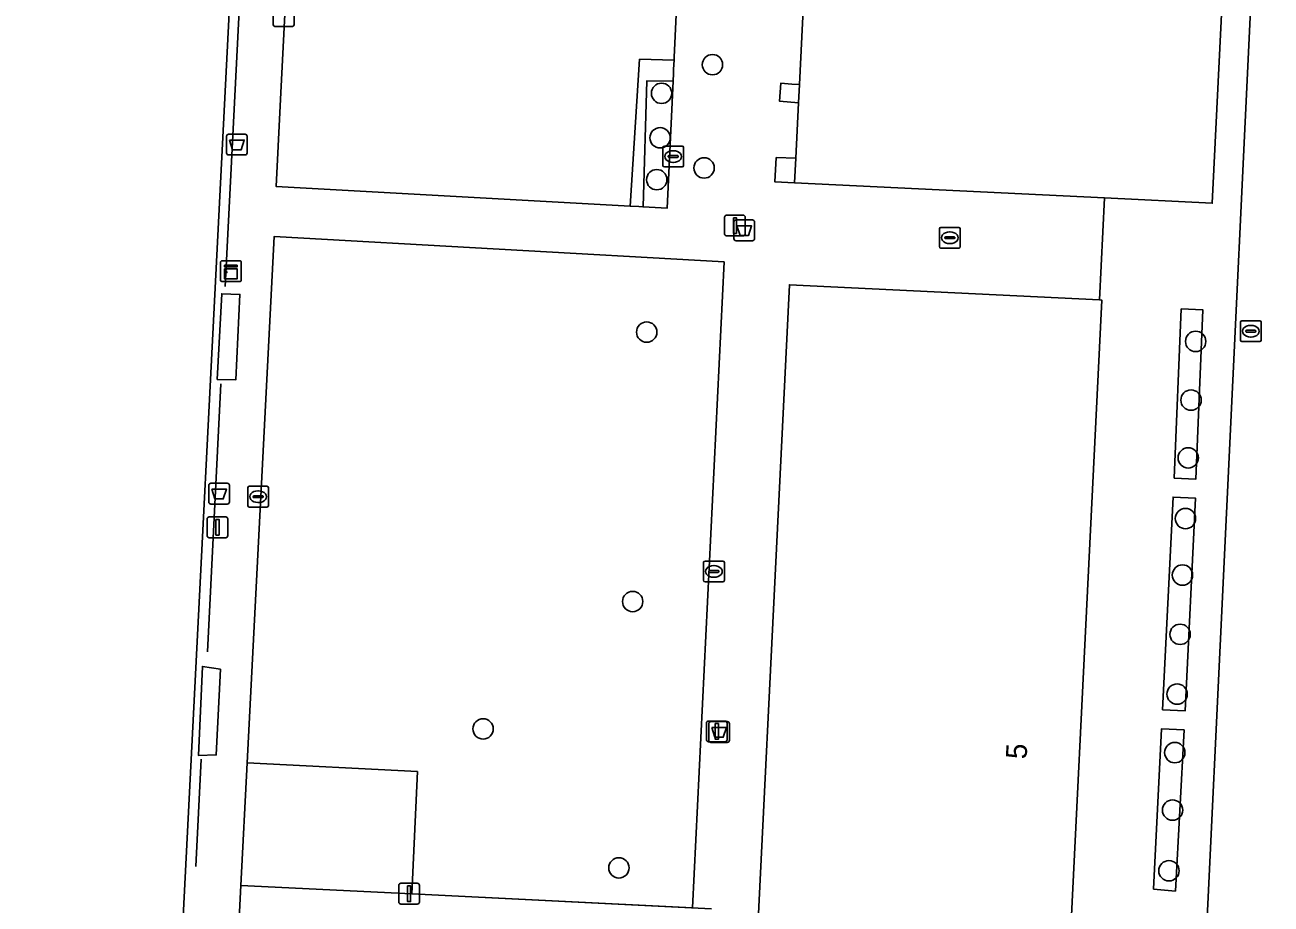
# Model space of a CAD drawing. Extents: x 161758 to 162722, y 384793 to 385405.
# Drawn here: x 162339.8 to 162399.6, y 385038.7 to 385080.9 of the extents above; entities that cross this region are included whole.
import ezdxf

# ---------------------------------------------------------------- set-up
doc = ezdxf.new("R2010")
doc.units = 0
for name, color, linetype in [('IMGEO_Afvalbak', 7, 'Continuous'), ('IMGEO_Boom', 7, 'Continuous'), ('IMGEO_Groenvoorziening', 7, 'Continuous'), ('IMGEO_Haag', 7, 'Continuous'), ('IMGEO_Hek', 7, 'Continuous'), ('IMGEO_Kast', 7, 'Continuous'), ('IMGEO_Kolk', 7, 'Continuous'), ('IMGEO_Lichtmast', 7, 'Continuous'), ('IMGEO_Pand', 7, 'Continuous'), ('IMGEO_Pand_nummerreeks', 7, 'Continuous'), ('IMGEO_Rioolput', 7, 'Continuous'), ('IMGEO_Terreindeel_open', 7, 'Continuous'), ('IMGEO_Voetpad_open', 7, 'Continuous')]:
    doc.layers.add(name, color=color, linetype=linetype)

msp = doc.modelspace()

# ---------------------------------------------------------------- linework, layer by layer
at = {"layer": 'IMGEO_Afvalbak'}
for p, q in [((162349.493, 385074.776), (162349.493, 385075.576)), ((162349.493, 385075.576), (162349.493, 385074.776)), ((162349.593, 385075.676), (162350.383, 385075.676)), ((162350.383, 385075.676), (162349.593, 385075.676)), ((162350.483, 385075.576), (162350.483, 385074.776)), ((162350.483, 385074.776), (162350.483, 385075.576)), ((162350.383, 385074.676), (162349.593, 385074.676)), ((162349.593, 385074.676), (162350.383, 385074.676)), ((162373.853, 385070.657), (162373.853, 385071.457)), ((162373.853, 385071.457), (162373.853, 385070.657)), ((162373.953, 385071.557), (162374.743, 385071.557)), ((162374.743, 385071.557), (162373.953, 385071.557)), ((162374.843, 385071.457), (162374.843, 385070.657)), ((162374.843, 385070.657), (162374.843, 385071.457)), ((162374.743, 385070.557), (162373.953, 385070.557)), ((162373.953, 385070.557), (162374.743, 385070.557)), ((162348.638, 385058.009), (162348.638, 385058.809)), ((162348.638, 385058.809), (162348.638, 385058.009)), ((162348.738, 385058.909), (162349.528, 385058.909)), ((162349.528, 385058.909), (162348.738, 385058.909)), ((162349.628, 385058.809), (162349.628, 385058.009)), ((162349.628, 385058.009), (162349.628, 385058.809)), ((162349.528, 385057.909), (162348.738, 385057.909)), ((162348.738, 385057.909), (162349.528, 385057.909)), ((162372.645, 385046.557), (162372.645, 385047.357)), ((162372.645, 385047.357), (162372.645, 385046.557)), ((162372.745, 385047.457), (162373.535, 385047.457)), ((162373.535, 385047.457), (162372.745, 385047.457)), ((162373.635, 385047.357), (162373.635, 385046.557)), ((162373.635, 385046.557), (162373.635, 385047.357)), ((162373.535, 385046.457), (162372.745, 385046.457)), ((162372.745, 385046.457), (162373.535, 385046.457))]:
    msp.add_line(p, q, dxfattribs=at)
for points in [[(162349.636, 385075.39), (162350.34, 385075.39), (162350.191, 385074.92), (162349.785, 385074.92), (162349.636, 385075.39)], [(162373.996, 385071.271), (162374.7, 385071.271), (162374.551, 385070.801), (162374.145, 385070.801), (162373.996, 385071.271)], [(162348.781, 385058.623), (162349.485, 385058.623), (162349.336, 385058.153), (162348.93, 385058.153), (162348.781, 385058.623)], [(162372.788, 385047.171), (162373.492, 385047.171), (162373.343, 385046.701), (162372.937, 385046.701), (162372.788, 385047.171)]]:
    msp.add_lwpolyline(points, dxfattribs=at)
for centre, start, end in [((162349.593, 385075.576), 90, 180), ((162349.593, 385075.576), 90, 180), ((162350.383, 385075.576), 0, 90), ((162350.383, 385075.576), 360, 90), ((162349.593, 385074.776), 180, 270), ((162349.593, 385074.776), 180, 270), ((162350.383, 385074.776), 270, 0), ((162350.383, 385074.776), 270, 0), ((162373.953, 385071.457), 90, 180), ((162373.953, 385071.457), 90, 180), ((162374.743, 385071.457), 0, 90), ((162374.743, 385071.457), 360, 90), ((162373.953, 385070.657), 180, 270), ((162373.953, 385070.657), 180, 270), ((162374.743, 385070.657), 270, 0), ((162374.743, 385070.657), 270, 0), ((162348.738, 385058.809), 90, 180), ((162348.738, 385058.809), 90, 180), ((162349.528, 385058.809), 0, 90), ((162349.528, 385058.809), 360, 90), ((162348.738, 385058.009), 180, 270), ((162348.738, 385058.009), 180, 270), ((162349.528, 385058.009), 270, 0), ((162349.528, 385058.009), 270, 0), ((162372.745, 385047.357), 90, 180), ((162372.745, 385047.357), 90, 180), ((162373.535, 385047.357), 0, 90), ((162373.535, 385047.357), 360, 90), ((162372.745, 385046.557), 180, 270), ((162372.745, 385046.557), 180, 270), ((162373.535, 385046.557), 270, 0), ((162373.535, 385046.557), 270, 0)]:
    msp.add_arc(centre, 0.1, start, end, dxfattribs=at)
at = {"layer": 'IMGEO_Boom'}
for centre in [(162372.823, 385079.014), (162370.38, 385077.639), (162370.308, 385075.501), (162372.42, 385074.053), (162370.146, 385073.49), (162369.665, 385066.169), (162396.02, 385065.722), (162395.798, 385062.901), (162395.663, 385060.125), (162395.531, 385057.208), (162395.387, 385054.497), (162368.992, 385053.223), (162395.273, 385051.648), (162395.13, 385048.778), (162361.809, 385047.104), (162395.018, 385045.966), (162394.914, 385043.207), (162368.33, 385040.429), (162394.739, 385040.291)]:
    msp.add_circle(centre, 0.489, dxfattribs=at)
at = {"layer": 'IMGEO_Groenvoorziening'}
msp.add_lwpolyline([(162353.845, 385111.893), (162352.061, 385077.041), (162351.881, 385073.156), (162368.869, 385072.219), (162369.32, 385079.274), (162370.979, 385079.226), (162370.986, 385079.375), (162371.082, 385081.416)], dxfattribs=at)
for points in [[(162370.931, 385078.223), (162370.949, 385078.593), (162370.958, 385078.793), (162370.979, 385079.226), (162369.32, 385079.274), (162368.869, 385072.219), (162369.289, 385072.196), (162369.489, 385072.185), (162369.672, 385078.24)], [(162370.931, 385078.223), (162369.672, 385078.24), (162369.489, 385072.185), (162370.642, 385072.121)], [(162376.996, 385078.06), (162376.628, 385078.086), (162376.1, 385078.123), (162376.047, 385077.257), (162376.953, 385077.182)], [(162376.822, 385074.53), (162375.882, 385074.555), (162375.811, 385073.388), (162376.764, 385073.346)], [(162373.384, 385069.543), (162351.779, 385070.756), (162350.477, 385045.47), (162358.655, 385045.052), (162358.391, 385039.179), (162371.859, 385038.506)], [(162396.368, 385067.236), (162395.326, 385067.279), (162394.991, 385059.153), (162396.033, 385059.11)], [(162396.02, 385058.186), (162394.94, 385058.24), (162394.429, 385048.024), (162395.509, 385047.97)], [(162395.464, 385047.056), (162394.385, 385047.109), (162394, 385039.407), (162395.052, 385039.311)]]:
    msp.add_lwpolyline(points, close=True, dxfattribs=at)
at = {"layer": 'IMGEO_Haag'}
for points in [[(162369.672, 385078.24), (162370.931, 385078.223), (162370.949, 385078.593), (162370.958, 385078.793), (162370.979, 385079.226), (162369.32, 385079.274), (162368.869, 385072.219), (162369.289, 385072.196), (162369.489, 385072.185)], [(162396.368, 385067.236), (162395.326, 385067.279), (162394.991, 385059.153), (162396.033, 385059.11)], [(162396.02, 385058.186), (162394.94, 385058.24), (162394.429, 385048.024), (162395.509, 385047.97)], [(162395.464, 385047.056), (162394.385, 385047.109), (162394, 385039.407), (162395.052, 385039.311)]]:
    msp.add_lwpolyline(points, close=True, dxfattribs=at)
at = {"layer": 'IMGEO_Hek'}
for points in [[(162349.435, 385068.365), (162351.591, 385110.949), (162328.352, 385112.223)], [(162391.403, 385067.713), (162391.641, 385072.611)], [(162348.578, 385050.813), (162349.22, 385063.679)], [(162348.022, 385040.498), (162348.27, 385045.648)], [(162344.943, 384881.973), (162351.819, 385022.72), (162349.339, 385022.849), (162350.174, 385039.589), (162358.391, 385039.179), (162372.781, 385038.462)]]:
    msp.add_lwpolyline(points, dxfattribs=at)
at = {"layer": 'IMGEO_Kast'}
for p, q in [((162349.201, 385068.668), (162349.201, 385069.509)), ((162349.201, 385069.509), (162349.201, 385068.668)), ((162349.276, 385069.593), (162350.117, 385069.593)), ((162350.117, 385069.593), (162349.276, 385069.593)), ((162350.201, 385069.518), (162350.201, 385068.677)), ((162350.201, 385068.677), (162350.201, 385069.518)), ((162350.126, 385068.593), (162349.285, 385068.593)), ((162349.285, 385068.593), (162350.126, 385068.593))]:
    msp.add_line(p, q, dxfattribs=at)
for points in [[(162349.396, 385069.383), (162349.996, 385069.383), (162349.996, 385069.298), (162349.396, 385069.298), (162349.396, 385069.383)], [(162349.396, 385069.208), (162349.996, 385069.208), (162349.996, 385068.719), (162349.396, 385068.719), (162349.396, 385069.208)]]:
    msp.add_lwpolyline(points, dxfattribs=at)
msp.add_circle((162349.48, 385069.057), 0.0377, dxfattribs=at)
for centre, start, end in [((162349.279, 385069.515), 92.4484, 184.28452), ((162349.279, 385069.515), 92.4484, 184.28452), ((162350.123, 385069.515), 2.4484, 94.28452), ((162350.123, 385069.515), 2.4484, 94.28452), ((162349.279, 385068.671), 182.4484, 274.28452), ((162349.279, 385068.671), 182.4484, 274.28452), ((162350.123, 385068.671), 272.4484, 4.28452), ((162350.123, 385068.671), 272.4484, 4.28452)]:
    msp.add_arc(centre, 0.0779, start, end, dxfattribs=at)
at = {"layer": 'IMGEO_Kolk'}
for p, q in [((162351.736, 385080.925), (162351.736, 385081.777)), ((162352.737, 385081.777), (162352.737, 385080.925)), ((162352.663, 385080.851), (162351.811, 385080.851)), ((162370.437, 385074.176), (162370.437, 385075.028)), ((162370.512, 385075.102), (162371.364, 385075.102)), ((162370.925, 385074.882), (162370.95, 385074.882)), ((162371.438, 385075.028), (162371.438, 385074.176)), ((162370.696, 385074.596), (162370.696, 385074.608)), ((162371.134, 385074.559), (162370.736, 385074.559)), ((162370.739, 385074.645), (162371.137, 385074.645)), ((162370.948, 385074.322), (162370.923, 385074.322)), ((162371.18, 385074.608), (162371.18, 385074.596)), ((162371.364, 385074.102), (162370.512, 385074.102)), ((162383.719, 385070.274), (162383.719, 385071.126)), ((162383.794, 385071.2), (162384.646, 385071.2)), ((162383.978, 385070.694), (162383.978, 385070.706)), ((162384.416, 385070.657), (162384.018, 385070.657)), ((162384.021, 385070.743), (162384.419, 385070.743)), ((162384.207, 385070.98), (162384.232, 385070.98)), ((162384.462, 385070.706), (162384.462, 385070.694)), ((162384.72, 385071.126), (162384.72, 385070.274)), ((162384.646, 385070.2), (162383.794, 385070.2)), ((162384.23, 385070.42), (162384.205, 385070.42)), ((162350.583, 385058.76), (162351.435, 385058.76)), ((162350.508, 385057.834), (162350.508, 385058.686)), ((162350.767, 385058.254), (162350.767, 385058.266)), ((162351.205, 385058.217), (162350.807, 385058.217)), ((162350.81, 385058.303), (162351.208, 385058.303)), ((162350.996, 385058.54), (162351.021, 385058.54)), ((162351.251, 385058.266), (162351.251, 385058.254)), ((162351.509, 385058.686), (162351.509, 385057.834)), ((162351.435, 385057.76), (162350.583, 385057.76)), ((162351.019, 385057.98), (162350.994, 385057.98)), ((162372.467, 385055.169), (162373.319, 385055.169)), ((162372.392, 385054.243), (162372.392, 385055.095)), ((162372.651, 385054.663), (162372.651, 385054.675)), ((162373.089, 385054.626), (162372.691, 385054.626)), ((162372.694, 385054.712), (162373.092, 385054.712)), ((162372.88, 385054.949), (162372.905, 385054.949)), ((162373.135, 385054.675), (162373.135, 385054.663)), ((162373.393, 385055.095), (162373.393, 385054.243)), ((162373.319, 385054.169), (162372.467, 385054.169)), ((162372.903, 385054.389), (162372.878, 385054.389))]:
    msp.add_line(p, q, dxfattribs=at)
for points in [[(162351.736, 385080.925), (162351.736, 385081.777)], [(162352.737, 385081.777), (162352.737, 385080.925)], [(162352.663, 385080.851), (162351.811, 385080.851)], [(162370.437, 385074.176), (162370.437, 385075.028)], [(162370.512, 385075.102), (162371.364, 385075.102)], [(162371.438, 385075.028), (162371.438, 385074.176)], [(162371.364, 385074.102), (162370.512, 385074.102)], [(162383.719, 385070.274), (162383.719, 385071.126)], [(162383.794, 385071.2), (162384.646, 385071.2)], [(162384.72, 385071.126), (162384.72, 385070.274)], [(162384.646, 385070.2), (162383.794, 385070.2)], [(162350.583, 385058.76), (162351.435, 385058.76)], [(162350.508, 385057.834), (162350.508, 385058.686)], [(162351.509, 385058.686), (162351.509, 385057.834)], [(162351.435, 385057.76), (162350.583, 385057.76)], [(162372.467, 385055.169), (162373.319, 385055.169)], [(162372.392, 385054.243), (162372.392, 385055.095)], [(162373.393, 385055.095), (162373.393, 385054.243)], [(162373.319, 385054.169), (162372.467, 385054.169)]]:
    msp.add_lwpolyline(points, dxfattribs=at)
for centre, radius, start, end in [((162351.813, 385080.927), 0.0765, 181.55205, 268.44795), ((162351.813, 385080.927), 0.0765, 181.55205, 268.44795), ((162352.661, 385080.927), 0.0765, 271.55205, 358.44795), ((162352.661, 385080.927), 0.0765, 271.55205, 358.44795), ((162370.514, 385075.026), 0.0765, 91.55205, 178.44795), ((162370.514, 385075.026), 0.0765, 91.55205, 178.44795), ((162371.362, 385075.026), 0.0765, 1.55205, 88.44795), ((162371.362, 385075.026), 0.0765, 1.55205, 88.44795), ((162370.736, 385074.605), 0.0403, 85.87752, 175.75265), ((162370.733, 385074.595), 0.0366, 178.93798, 274.71019), ((162371.137, 385074.602), 0.043, 264.86636, 352.45326), ((162371.141, 385074.607), 0.0386, 1.73085, 96.63898), ((162370.514, 385074.178), 0.0765, 181.55205, 268.44795), ((162370.514, 385074.178), 0.0765, 181.55205, 268.44795), ((162371.362, 385074.178), 0.0765, 271.55205, 358.44795), ((162371.362, 385074.178), 0.0765, 271.55205, 358.44795), ((162383.796, 385071.124), 0.0765, 91.55205, 178.44795), ((162383.796, 385071.124), 0.0765, 91.55205, 178.44795), ((162384.018, 385070.703), 0.0403, 85.87752, 175.75265), ((162384.015, 385070.693), 0.0366, 178.93798, 274.71019), ((162384.419, 385070.7), 0.043, 264.86636, 352.45326), ((162384.423, 385070.705), 0.0386, 1.73085, 96.63898), ((162384.644, 385071.124), 0.0765, 1.55205, 88.44795), ((162384.644, 385071.124), 0.0765, 1.55205, 88.44795), ((162383.796, 385070.276), 0.0765, 181.55205, 268.44795), ((162383.796, 385070.276), 0.0765, 181.55205, 268.44795), ((162384.644, 385070.276), 0.0765, 271.55205, 358.44795), ((162384.644, 385070.276), 0.0765, 271.55205, 358.44795), ((162350.585, 385058.684), 0.0765, 91.55205, 178.44795), ((162350.585, 385058.684), 0.0765, 91.55205, 178.44795), ((162351.433, 385058.684), 0.0765, 1.55205, 88.44795), ((162351.433, 385058.684), 0.0765, 1.55205, 88.44795), ((162350.807, 385058.263), 0.0403, 85.87752, 175.75265), ((162350.804, 385058.253), 0.0366, 178.93798, 274.71019), ((162351.208, 385058.26), 0.043, 264.86636, 352.45326), ((162351.212, 385058.265), 0.0386, 1.73085, 96.63898), ((162350.585, 385057.836), 0.0765, 181.55205, 268.44795), ((162350.585, 385057.836), 0.0765, 181.55205, 268.44795), ((162351.433, 385057.836), 0.0765, 271.55205, 358.44795), ((162351.433, 385057.836), 0.0765, 271.55205, 358.44795), ((162372.469, 385055.093), 0.0765, 91.55205, 178.44795), ((162372.469, 385055.093), 0.0765, 91.55205, 178.44795), ((162373.317, 385055.093), 0.0765, 1.55205, 88.44795), ((162373.317, 385055.093), 0.0765, 1.55205, 88.44795), ((162372.691, 385054.672), 0.0403, 85.87752, 175.75265), ((162372.688, 385054.662), 0.0366, 178.93798, 274.71019), ((162373.092, 385054.669), 0.043, 264.86636, 352.45326), ((162373.096, 385054.674), 0.0386, 1.73085, 96.63898), ((162372.469, 385054.245), 0.0765, 181.55205, 268.44795), ((162372.469, 385054.245), 0.0765, 181.55205, 268.44795), ((162373.317, 385054.245), 0.0765, 271.55205, 358.44795), ((162373.317, 385054.245), 0.0765, 271.55205, 358.44795)]:
    msp.add_arc(centre, radius, start, end, dxfattribs=at)
for centre, major_axis, ratio, start_param, end_param in [((162370.924, 385074.602), (-0.387, 0.002), 0.722429, 4.712389, 7.853982), ((162370.949, 385074.602), (-0.39, 0.002), 0.717154, 1.570796, 4.712389), ((162384.206, 385070.7), (-0.387, 0.002), 0.722429, 4.712389, 7.853982), ((162384.231, 385070.7), (-0.39, 0.002), 0.717154, 1.570796, 4.712389), ((162350.995, 385058.26), (-0.387, 0.002), 0.722429, 4.712389, 7.853982), ((162351.02, 385058.26), (-0.39, 0.002), 0.717154, 1.570796, 4.712389), ((162372.879, 385054.669), (-0.387, 0.002), 0.722429, 4.712389, 7.853982), ((162372.904, 385054.669), (-0.39, 0.002), 0.717154, 1.570796, 4.712389)]:
    msp.add_ellipse(centre, major_axis=major_axis, ratio=ratio, start_param=start_param, end_param=end_param, dxfattribs=at)
at = {"layer": 'IMGEO_Lichtmast'}
for p, q in [((162373.406, 385070.887), (162373.406, 385071.687)), ((162373.406, 385071.687), (162373.406, 385070.887)), ((162373.506, 385071.787), (162374.296, 385071.787)), ((162374.296, 385071.787), (162373.506, 385071.787)), ((162374.396, 385071.687), (162374.396, 385070.887)), ((162374.396, 385070.887), (162374.396, 385071.687)), ((162374.296, 385070.787), (162373.506, 385070.787)), ((162373.506, 385070.787), (162374.296, 385070.787)), ((162348.562, 385056.391), (162348.562, 385057.191)), ((162348.562, 385057.191), (162348.562, 385056.391)), ((162348.662, 385057.291), (162349.452, 385057.291)), ((162349.452, 385057.291), (162348.662, 385057.291)), ((162349.552, 385057.191), (162349.552, 385056.391)), ((162349.552, 385056.391), (162349.552, 385057.191)), ((162349.452, 385056.291), (162348.662, 385056.291)), ((162348.662, 385056.291), (162349.452, 385056.291)), ((162372.536, 385046.585), (162372.536, 385047.385)), ((162372.536, 385047.385), (162372.536, 385046.585)), ((162372.636, 385047.485), (162373.426, 385047.485)), ((162373.426, 385047.485), (162372.636, 385047.485)), ((162373.526, 385047.385), (162373.526, 385046.585)), ((162373.526, 385046.585), (162373.526, 385047.385)), ((162373.426, 385046.485), (162372.636, 385046.485)), ((162372.636, 385046.485), (162373.426, 385046.485)), ((162357.762, 385038.789), (162357.762, 385039.589)), ((162357.762, 385039.589), (162357.762, 385038.789)), ((162357.862, 385039.689), (162358.652, 385039.689)), ((162358.652, 385039.689), (162357.862, 385039.689)), ((162358.752, 385039.589), (162358.752, 385038.789)), ((162358.752, 385038.789), (162358.752, 385039.589)), ((162358.652, 385038.689), (162357.862, 385038.689)), ((162357.862, 385038.689), (162358.652, 385038.689))]:
    msp.add_line(p, q, dxfattribs=at)
for points in [[(162373.826, 385071.662), (162373.976, 385071.662), (162373.976, 385070.912), (162373.826, 385070.912), (162373.826, 385071.662)], [(162348.982, 385057.166), (162349.132, 385057.166), (162349.132, 385056.416), (162348.982, 385056.416), (162348.982, 385057.166)], [(162372.956, 385047.36), (162373.106, 385047.36), (162373.106, 385046.61), (162372.956, 385046.61), (162372.956, 385047.36)], [(162358.182, 385039.564), (162358.332, 385039.564), (162358.332, 385038.814), (162358.182, 385038.814), (162358.182, 385039.564)]]:
    msp.add_lwpolyline(points, dxfattribs=at)
for centre, start, end in [((162373.506, 385071.687), 90, 180), ((162373.506, 385071.687), 90, 180), ((162374.296, 385071.687), 0, 90), ((162374.296, 385071.687), 360, 90), ((162373.506, 385070.887), 180, 270), ((162373.506, 385070.887), 180, 270), ((162374.296, 385070.887), 270, 0), ((162374.296, 385070.887), 270, 0), ((162348.662, 385057.191), 90, 180), ((162348.662, 385057.191), 90, 180), ((162349.452, 385057.191), 0, 90), ((162349.452, 385057.191), 360, 90), ((162348.662, 385056.391), 180, 270), ((162348.662, 385056.391), 180, 270), ((162349.452, 385056.391), 270, 0), ((162349.452, 385056.391), 270, 0), ((162372.636, 385047.385), 90, 180), ((162372.636, 385047.385), 90, 180), ((162373.426, 385047.385), 0, 90), ((162373.426, 385047.385), 360, 90), ((162372.636, 385046.585), 180, 270), ((162372.636, 385046.585), 180, 270), ((162373.426, 385046.585), 270, 0), ((162373.426, 385046.585), 270, 0), ((162357.862, 385039.589), 90, 180), ((162357.862, 385039.589), 90, 180), ((162358.652, 385039.589), 0, 90), ((162358.652, 385039.589), 360, 90), ((162357.862, 385038.789), 180, 270), ((162357.862, 385038.789), 180, 270), ((162358.652, 385038.789), 270, 0), ((162358.652, 385038.789), 270, 0)]:
    msp.add_arc(centre, 0.1, start, end, dxfattribs=at)
at = {"layer": 'IMGEO_Pand'}
for points in [[(162398.207, 385100.548), (162387.283, 385101.087), (162378.156, 385101.538), (162377.464, 385087.529), (162377.462, 385087.485), (162377.453, 385087.31), (162377.415, 385086.541), (162377.292, 385084.054), (162377.19, 385081.987), (162376.996, 385078.06), (162376.953, 385077.182), (162376.822, 385074.53), (162376.764, 385073.346), (162391.641, 385072.611), (162396.815, 385072.356)], [(162391.509, 385067.708), (162391.403, 385067.713), (162376.514, 385068.444), (162374.363, 385024.591), (162389.358, 385023.855)]]:
    msp.add_lwpolyline(points, close=True, dxfattribs=at)
at = {"layer": 'IMGEO_Rioolput'}
for p, q in [((162398.169, 385065.785), (162398.169, 385066.637)), ((162398.244, 385066.711), (162399.096, 385066.711)), ((162398.657, 385066.491), (162398.682, 385066.491)), ((162399.17, 385066.637), (162399.17, 385065.785)), ((162398.428, 385066.205), (162398.428, 385066.217)), ((162398.866, 385066.168), (162398.468, 385066.168)), ((162398.471, 385066.254), (162398.869, 385066.254)), ((162398.68, 385065.931), (162398.655, 385065.931)), ((162398.912, 385066.217), (162398.912, 385066.205)), ((162399.096, 385065.711), (162398.244, 385065.711))]:
    msp.add_line(p, q, dxfattribs=at)
for points in [[(162398.169, 385065.785), (162398.169, 385066.637)], [(162398.244, 385066.711), (162399.096, 385066.711)], [(162399.17, 385066.637), (162399.17, 385065.785)], [(162399.096, 385065.711), (162398.244, 385065.711)]]:
    msp.add_lwpolyline(points, dxfattribs=at)
for centre, radius, start, end in [((162398.246, 385066.635), 0.0765, 91.55205, 178.44795), ((162398.246, 385066.635), 0.0765, 91.55205, 178.44795), ((162399.094, 385066.635), 0.0765, 1.55205, 88.44795), ((162399.094, 385066.635), 0.0765, 1.55205, 88.44795), ((162398.468, 385066.214), 0.0403, 85.87752, 175.75265), ((162398.465, 385066.204), 0.0366, 178.93798, 274.71019), ((162398.869, 385066.211), 0.043, 264.86636, 352.45326), ((162398.873, 385066.216), 0.0386, 1.73085, 96.63898), ((162398.246, 385065.787), 0.0765, 181.55205, 268.44795), ((162398.246, 385065.787), 0.0765, 181.55205, 268.44795), ((162399.094, 385065.787), 0.0765, 271.55205, 358.44795), ((162399.094, 385065.787), 0.0765, 271.55205, 358.44795)]:
    msp.add_arc(centre, radius, start, end, dxfattribs=at)
for centre, major_axis, ratio, start_param, end_param in [((162398.656, 385066.211), (-0.387, 0.002), 0.722429, 4.712389, 7.853982), ((162398.681, 385066.211), (-0.39, 0.002), 0.717154, 1.570796, 4.712389)]:
    msp.add_ellipse(centre, major_axis=major_axis, ratio=ratio, start_param=start_param, end_param=end_param, dxfattribs=at)
at = {"layer": 'IMGEO_Terreindeel_open'}
msp.add_lwpolyline([(162351.088, 385110.479), (162280.002, 385114.097), (162274.486, 385006.971), (162345.645, 385003.41), (162347.606, 385041.859)], close=True, dxfattribs=at)
at = {"layer": 'IMGEO_Voetpad_open'}
for points in [[(162347.606, 385041.859), (162345.645, 385003.41), (162274.486, 385006.971), (162280.002, 385114.097), (162351.088, 385110.479)], [(162404.495, 385069.287), (162405.806, 385097.791), (162404.241, 385097.842), (162404.247, 385098.213), (162399.452, 385098.409), (162395.555, 385016.551), (162408.86, 385034.446), (162400.443, 385034.857), (162400.64, 385038.778), (162402.942, 385038.647), (162404.199, 385063.991), (162405.414, 385063.918), (162405.573, 385068.801), (162405.588, 385069.236)], [(162350.174, 385039.589), (162350.477, 385045.47), (162351.779, 385070.756), (162373.384, 385069.543), (162371.859, 385038.506), (162358.391, 385039.179)], [(162376.514, 385068.444), (162391.403, 385067.713), (162391.509, 385067.708), (162389.358, 385023.855), (162374.363, 385024.591)], [(162350.132, 385067.98), (162349.26, 385068.008), (162349.05, 385063.898), (162349.939, 385063.87)], [(162349.939, 385063.87), (162349.05, 385063.898), (162349.26, 385068.008), (162350.132, 385067.98)], [(162395.326, 385067.279), (162396.368, 385067.236), (162396.033, 385059.11), (162394.991, 385059.153)], [(162394.94, 385058.24), (162396.02, 385058.186), (162395.509, 385047.97), (162394.429, 385048.024)], [(162349.201, 385049.972), (162348.334, 385050.105), (162348.147, 385045.822), (162348.996, 385045.857)], [(162348.996, 385045.857), (162348.147, 385045.822), (162348.334, 385050.105), (162349.201, 385049.972)], [(162394.385, 385047.109), (162395.464, 385047.056), (162395.052, 385039.311), (162394, 385039.407)], [(162350.477, 385045.47), (162350.174, 385039.589), (162358.391, 385039.179), (162358.655, 385045.052)]]:
    msp.add_lwpolyline(points, close=True, dxfattribs=at)
for points in [[(162371.082, 385081.416), (162370.986, 385079.375), (162370.979, 385079.226), (162370.958, 385078.793), (162370.949, 385078.593), (162370.931, 385078.223), (162370.642, 385072.121), (162369.489, 385072.185), (162369.289, 385072.196), (162368.869, 385072.219), (162351.881, 385073.156), (162352.061, 385077.041), (162353.845, 385111.893)], [(162398.207, 385100.548), (162396.815, 385072.356), (162391.641, 385072.611), (162376.764, 385073.346), (162375.811, 385073.388), (162375.882, 385074.555), (162376.822, 385074.53), (162376.953, 385077.182), (162376.047, 385077.257), (162376.1, 385078.123), (162376.628, 385078.086), (162376.996, 385078.06), (162377.19, 385081.987)], [(162341.935, 384896.184), (162343.176, 384919.896), (162344.286, 384941.926), (162345.185, 384956.752), (162345.258, 384958.203), (162347.307, 384999.346), (162347.453, 385001.785), (162348.094, 385001.752), (162350.623, 385001.623), (162350.814, 385005.828), (162348.468, 385005.944), (162348.547, 385007.536), (162349.339, 385022.849), (162351.76, 385022.721), (162370.976, 385021.702), (162370.918, 385020.647), (162351.703, 385021.65), (162351.579, 385018.803), (162353.477, 385018.706), (162395.555, 385016.551), (162399.452, 385098.409)]]:
    msp.add_lwpolyline(points, dxfattribs=at)

# ---------------------------------------------------------------- texts
at = {"layer": 'IMGEO_Pand_nummerreeks'}
msp.add_text('5', height=1, rotation=87.19188, dxfattribs=at).set_placement((162387.903, 385045.634))

doc.saveas('drawing.dxf')
